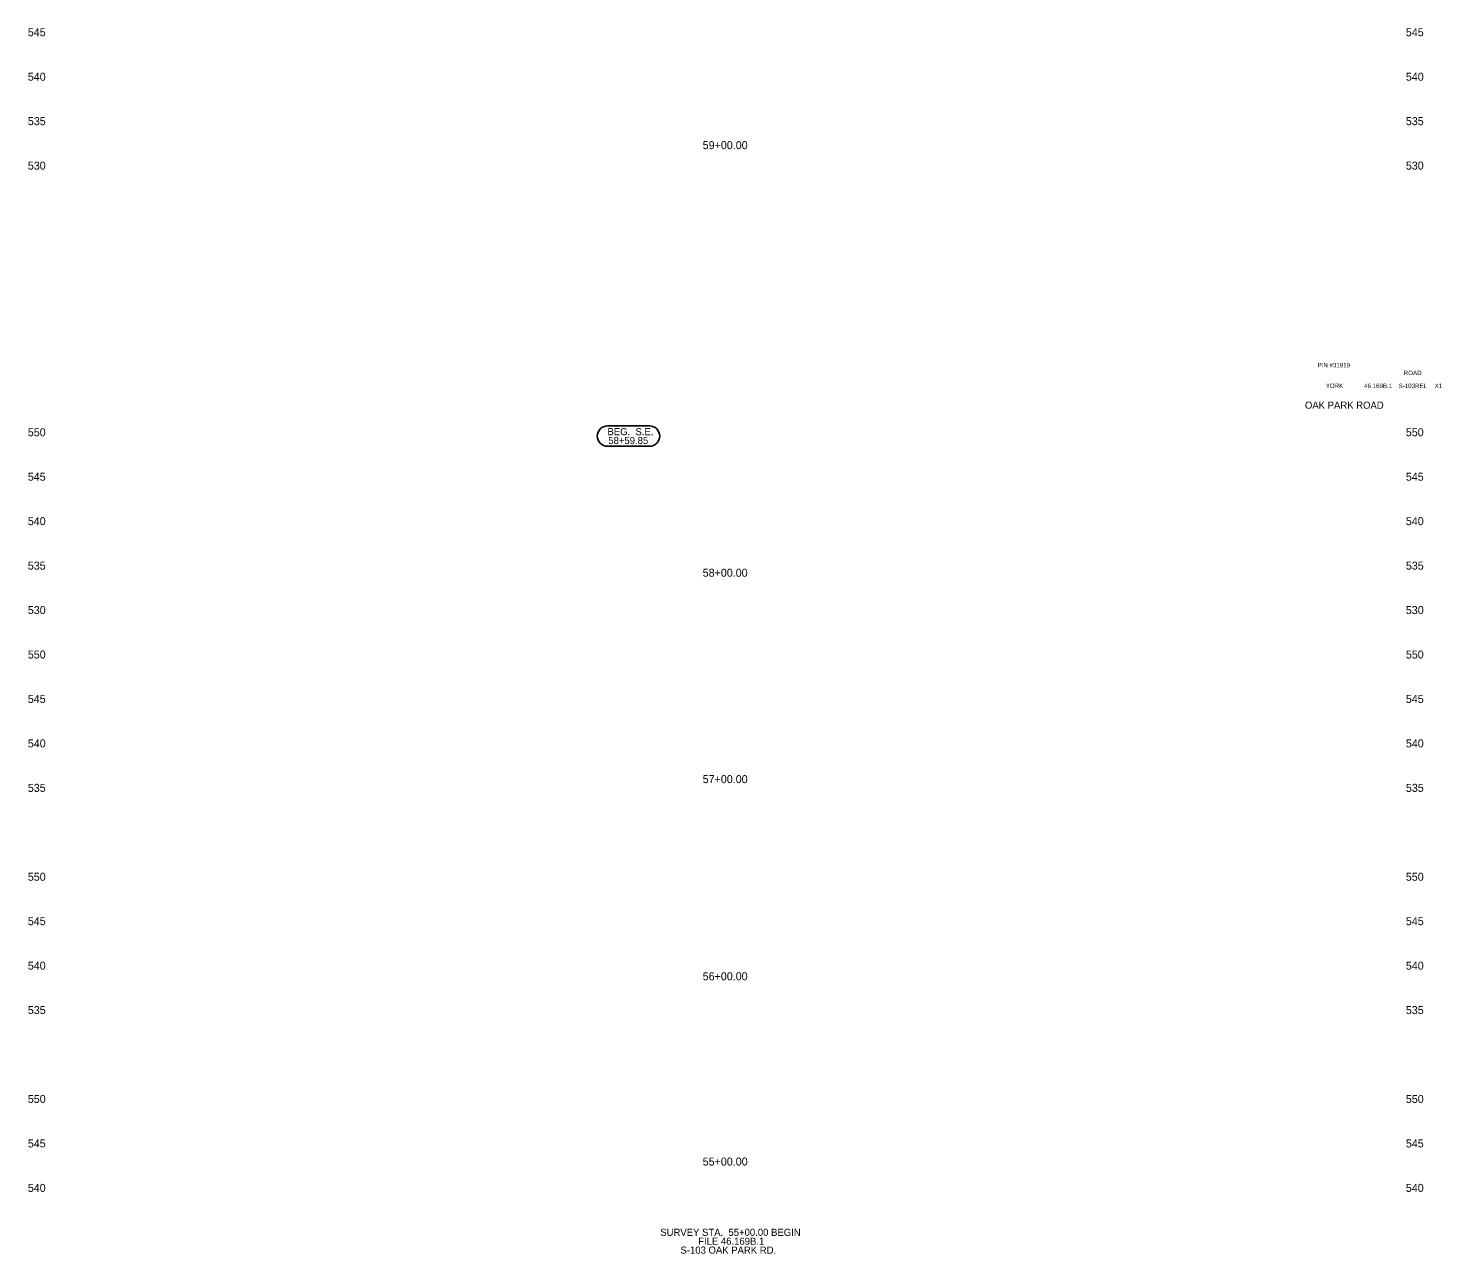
# Model space of a CAD drawing. Extents: x 1001 to 1160, y 1003 to 1563.
# Drawn here: x 1001.5 to 1160.5, y 1003 to 1140.9 of the extents above; entities that cross this region are included whole.
import ezdxf

# ---------------------------------------------------------------- set-up
doc = ezdxf.new("R2010")
doc.units = 0
for name, color, linetype in [('Level 25', 7, 'Continuous'), ('Level 41', 7, 'Continuous'), ('Level 56', 7, 'Continuous')]:
    doc.layers.add(name, color=color, linetype=linetype)

msp = doc.modelspace()

# ---------------------------------------------------------------- linework, layer by layer
at = {"layer": 'Level 41'}
for p, q in [((1071.37, 1096.17), (1066.65, 1096.17)), ((1066.65, 1093.87), (1071.37, 1093.87))]:
    msp.add_line(p, q, dxfattribs=at)
for centre, start, end in [((1066.65, 1095.02), 90, 270), ((1071.37, 1095.02), 270, 90)]:
    msp.add_arc(centre, 1.15, start, end, dxfattribs=at)

# ---------------------------------------------------------------- texts
at = {"layer": 'Level 25'}
for s, p in [('59+00.00', (1077.36, 1127.3)), ('58+00.00', (1077.36, 1079.2)), ('57+00.00', (1077.36, 1055.98)), ('56+00.00', (1077.36, 1033.8)), ('55+00.00', (1077.36, 1012.96))]:
    msp.add_text(s, height=0.9, dxfattribs=at).set_placement(p)
at = {"layer": 'Level 41'}
for s, height, p in [('PIN #31919', 0.5, (1146.52, 1102.75)), ('ROAD', 0.5, (1156.22, 1101.88)), ('YORK', 0.5, (1147.45, 1100.43)), ('46.169B.1', 0.5, (1151.76, 1100.43)), ('S-103REL', 0.5, (1155.64, 1100.43)), ('X1', 0.5, (1159.7, 1100.43)), ('OAK PARK ROAD', 0.8, (1145.1, 1098.1)), ('BEG.  S.E.', 0.8, (1066.65, 1095.12)), ('58+59.85', 0.8, (1066.74, 1094.12)), ('SURVEY STA.  55+00.00 BEGIN', 0.8, (1072.59, 1005.05)), ('FILE 46.169B.1', 0.8, (1076.85, 1004.05)), ('S-103 OAK PARK RD.', 0.8, (1074.86, 1003.05))]:
    msp.add_text(s, height=height, dxfattribs=at).set_placement(p)
at = {"layer": 'Level 56'}
for s, p in [('545', (1001.45, 1140)), ('545', (1156.45, 1140)), ('540', (1001.45, 1135)), ('540', (1156.45, 1135)), ('535', (1001.45, 1130)), ('535', (1156.45, 1130)), ('530', (1001.45, 1125)), ('530', (1156.45, 1125)), ('550', (1001.45, 1095)), ('550', (1156.45, 1095)), ('545', (1001.45, 1090)), ('545', (1156.45, 1090)), ('540', (1001.45, 1085)), ('540', (1156.45, 1085)), ('535', (1001.45, 1080)), ('535', (1156.45, 1080)), ('530', (1001.45, 1075)), ('530', (1156.45, 1075)), ('550', (1001.45, 1070)), ('550', (1156.45, 1070)), ('545', (1001.45, 1065)), ('545', (1156.45, 1065)), ('540', (1001.45, 1060)), ('540', (1156.45, 1060)), ('535', (1001.45, 1055)), ('535', (1156.45, 1055)), ('550', (1001.45, 1045)), ('550', (1156.45, 1045)), ('545', (1001.45, 1040)), ('545', (1156.45, 1040)), ('540', (1001.45, 1035)), ('540', (1156.45, 1035)), ('535', (1001.45, 1030)), ('535', (1156.45, 1030)), ('550', (1001.45, 1020)), ('550', (1156.45, 1020)), ('545', (1001.45, 1015)), ('545', (1156.45, 1015)), ('540', (1001.45, 1010)), ('540', (1156.45, 1010))]:
    msp.add_text(s, height=0.9, dxfattribs=at).set_placement(p)

doc.saveas('drawing.dxf')
